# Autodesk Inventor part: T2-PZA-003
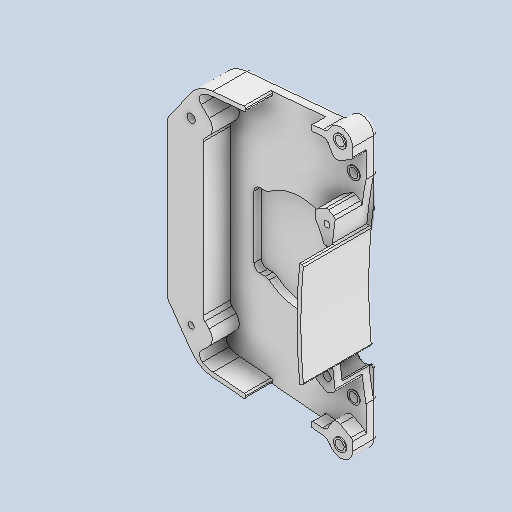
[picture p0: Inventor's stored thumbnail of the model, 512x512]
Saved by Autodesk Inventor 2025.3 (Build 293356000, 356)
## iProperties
Created: 2026-10
Part Number: T2-PZA-003
Material: Genérico
Description: Placa inferior del gripper
Document SubType Name: Modeling
Designer: Luis MuÃ±oz
Density: 1 g/cm^3
Appearance: Valor por defecto
Project: TESIS 2 - Plataforma mecatrÃ³nica preventiva desacoplada
Sending System: ONSHAPE BY PTC INC, 1.194
Preprocessor: ST-DEVELOPER v20
Material_Fabricacion: PLA
Title: Placa inferior del gripper
Revision Number: 00
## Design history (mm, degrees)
feature "Bottom_Plate"
sketch "Boceto2"
  geometry: L1 (0, 51.054)-(0, 0) reference; L2 (0, 0)-(11.5, 0) reference; L3 (11.5, 51.054)-(11.5, 0) reference; L4 (11.5, 51.054)-(0, 51.054) reference; C1 r 1.25 at (5.9, 47.527) reference; C2 r 1.25 at (5.9, 3.527) reference; C3 r 1.25 at (8.5, 25.527) reference; C4 r 2 at (5.9, 47.527); C5 r 2 at (8.5, 25.527); C6 r 1.25 at (5.9, 3.527) reference; C7 r 2 at (5.9, 3.527); 1 further point
  constraints: 3 centre point, 3 coincident
  dimensions: "d3" = 4 diameter of C4; "d4" = 4 diameter of C5; "d5" = 4 diameter of C7
extrude "Extrusión1" cut sketch "Boceto2" distance "d6" = 8; taper "d7" = 0 deg
node "Sólido1"
node "Contorno proyectado2"
